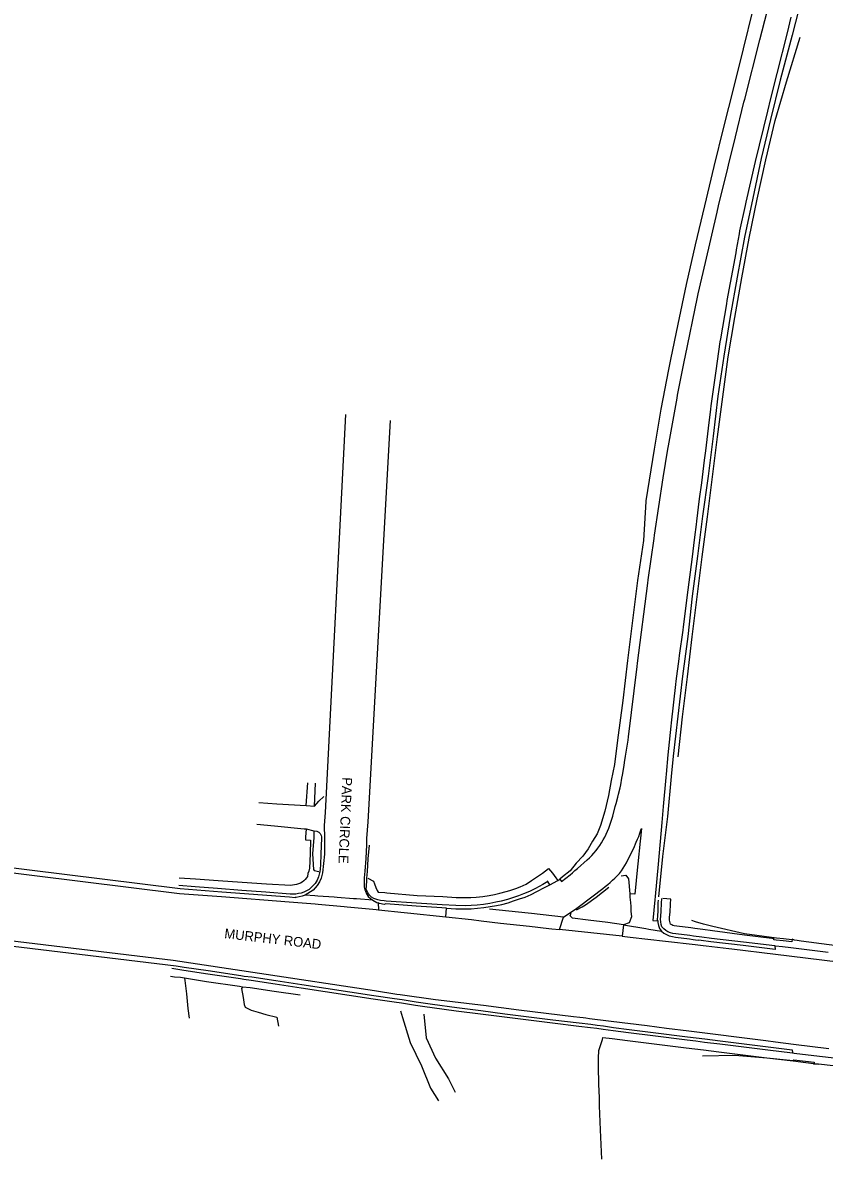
# Model space of a CAD drawing. Extents: x 1723992 to 1732080, y 650782 to 665122.
# Drawn here: x 1725049 to 1725545, y 658514 to 659218 of the extents above; entities that cross this region are included whole.
import ezdxf

# ---------------------------------------------------------------- set-up
doc = ezdxf.new("R2010")
doc.units = 0
for name, color, linetype in [('SURVEY - ROADSIDE BARRIERS with Text', 7, 'Continuous'), ('SURVEY - TRANSPORTATION - Features', 7, 'Continuous'), ('SURVEY - TRANSPORTATION - Roads', 7, 'Continuous'), ('SURVEY - TRANSPORTATION - Roads Text', 7, 'Continuous')]:
    doc.layers.add(name, color=color, linetype=linetype)

msp = doc.modelspace()

# ---------------------------------------------------------------- linework, layer by layer
at = {"layer": 'SURVEY - ROADSIDE BARRIERS with Text'}
for points in [[(1725454.31, 658763.66), (1725456.99, 658788.4), (1725459.98, 658813.11), (1725462.96, 658837.82), (1725466.03, 658862.66), (1725469.2, 658887.44), (1725472.36, 658912.25), (1725475.49, 658937), (1725478.58, 658961.8), (1725481.79, 658986.47), (1725485.28, 659011.19), (1725489.24, 659035.69), (1725493.56, 659060.19), (1725498.27, 659084.82), (1725503.18, 659108.92), (1725508.58, 659133.26), (1725514.22, 659157.6), (1725521.22, 659181.56), (1725529.7, 659209.3)], [(1725527.82, 658649.84), (1725524.68, 658650.2), (1725519.38, 658650.81), (1725515.12, 658651.27), (1725495.31, 658654.08), (1725475.79, 658658.48), (1725469.89, 658660.07), (1725465.02, 658661.42), (1725462.65, 658662.19)], [(1725749.44, 658623.21), (1725747.68, 658622.94), (1725746.17, 658622.95), (1725726.3, 658625.19), (1725706.43, 658627.62), (1725686.58, 658630.08), (1725666.74, 658632.53), (1725646.89, 658635.01), (1725627.04, 658637.46), (1725607.19, 658639.9), (1725587.34, 658642.33), (1725567.5, 658644.8), (1725547.65, 658647.26), (1725530.29, 658649.41), (1725527.82, 658649.88), (1725526.28, 658650.16), (1725524.75, 658650.8)], [(1725469.38, 658578.48), (1725489.23, 658578.95), (1725509.01, 658577.31), (1725525.44, 658575.33), (1725541.17, 658573.4)], [(1725762.72, 658545.48), (1725760.68, 658546.18), (1725739.67, 658549.03), (1725719.83, 658551.53), (1725699.98, 658553.97), (1725680.13, 658556.43), (1725660.28, 658558.86), (1725640.43, 658561.3), (1725620.59, 658563.76), (1725600.74, 658566.22), (1725580.89, 658568.65), (1725561.04, 658571.09), (1725541.17, 658573.41), (1725539.63, 658573.41), (1725538.14, 658573.13)]]:
    msp.add_lwpolyline(points, dxfattribs=at)
at = {"layer": 'SURVEY - TRANSPORTATION - Features'}
for p, q in [((1725224.17, 658733.51), (1725225.12, 658747.48)), ((1725229.25, 658733.05), (1725229.89, 658747.28))]:
    msp.add_line(p, q, dxfattribs=at)
for points in [[(1725530.96, 659234.75), (1725524.82, 659210.53), (1725517.39, 659182.52), (1725511.28, 659158.31), (1725505.65, 659133.97), (1725500.35, 659109.58), (1725495.28, 659085.33), (1725490.85, 659060.69), (1725486.48, 659036.15), (1725482.44, 659011.59), (1725478.8, 658986.89), (1725475.82, 658962.14), (1725472.77, 658937.34), (1725469.21, 658912.63), (1725466.19, 658887.82), (1725463.01, 658863.05), (1725460.29, 658838.18), (1725456.88, 658813.49), (1725454.08, 658788.72), (1725451.23, 658763.96), (1725449.9, 658751.51), (1725447.7, 658726.64), (1725444.57, 658701.81), (1725442.19, 658676.94)], [(1725500.51, 659226.33), (1725494.49, 659202.05), (1725488.39, 659177.82), (1725482.33, 659153.52), (1725476.4, 659129.19), (1725470.51, 659104.86), (1725464.75, 659080.55), (1725459.26, 659056.11), (1725454.01, 659031.55), (1725449.43, 659009.61), (1725448.21, 659003.5), (1725443.6, 658978.83), (1725439.32, 658954.08), (1725434.3, 658922.21), (1725434.2, 658921.72)], [(1725434.2, 658921.72), (1725432.9, 658897.64), (1725429.18, 658872.88), (1725426.08, 658848.07), (1725422.87, 658823.3), (1725419.94, 658798.44), (1725416.68, 658773.89), (1725414.77, 658758.79), (1725412.81, 658748.88), (1725411.09, 658739.69), (1725408.93, 658729.88), (1725406.23, 658721.07), (1725404.11, 658715.95), (1725401.34, 658711.36), (1725398.64, 658706.68), (1725395.19, 658702.16), (1725391.1, 658697.73), (1725387.35, 658693), (1725382.76, 658689.26), (1725380.99, 658687.83)], [(1724297.25, 658787.39), (1725146.15, 658682.02), (1725172, 658680.07), (1725213.89, 658676.86), (1725217.31, 658676.58)], [(1725194.75, 658735.42), (1725205.87, 658734.42), (1725224.17, 658733.51), (1725229.25, 658733.05), (1725231.89, 658736.17), (1725235.07, 658739.04)], [(1725224.09, 658718.95), (1725223.67, 658713.89), (1725223.64, 658712.3), (1725226.89, 658712.07), (1725226.6, 658703.64), (1725226.11, 658694.76), (1725225.7, 658692.77), (1725225.19, 658691.41), (1725225.04, 658689.47), (1725224.24, 658688.6), (1725223.41, 658687.75), (1725222.57, 658686.85), (1725221.6, 658686.08), (1725220.57, 658685.34), (1725219.39, 658684.94), (1725218.18, 658684.6), (1725216.95, 658684.33), (1725215.7, 658684.17), (1725214.58, 658684.03), (1725199.59, 658684.73), (1725184.62, 658685.76), (1725169.64, 658686.9), (1725155.71, 658687.89), (1725145.6, 658688.56)], [(1725193.49, 658721.99), (1725204.59, 658720.78), (1725222.81, 658719.04), (1725224.09, 658718.95), (1725228.9, 658717.87), (1725230.75, 658717.5), (1725231.86, 658716.93), (1725232.8, 658716.03), (1725233.41, 658714.97), (1725233.64, 658714.03), (1725233.66, 658713.45)], [(1724492.49, 658712.89), (1725143.68, 658634.29), (1725147.43, 658633.67), (1725148.68, 658633.43), (1725163.52, 658631.23), (1725183.79, 658628.22), (1725185.77, 658627.89), (1725190.47, 658627.28), (1725205.3, 658625.03), (1725221.41, 658622.63), (1725236.23, 658620.32), (1725251.06, 658618.09), (1725265.89, 658615.82), (1725278.79, 658613.91), (1725283.42, 658613.33), (1725292.15, 658611.97), (1725297.86, 658611.14), (1725302.27, 658610.39), (1725317.27, 658608.35), (1725332.15, 658606.48), (1725347.03, 658604.53), (1725361.91, 658602.7), (1725376.8, 658600.85), (1725393.02, 658598.89), (1725400.17, 658597.98), (1725404.14, 658597.47), (1725408.11, 658596.96), (1725414.26, 658596.09), (1725423.85, 658594.84), (1725438.73, 658592.93), (1725460.13, 658590.3), (1725465.41, 658589.62), (1725470.71, 658588.94), (1725480.29, 658587.75), (1725490.2, 658586.59), (1725509.95, 658584.05), (1725524.76, 658582.19), (1725524.93, 658580.3)], [(1725233.66, 658713.45), (1725233.22, 658703.41), (1725232.94, 658696.68), (1725232.73, 658694.15), (1725232.5, 658692.47), (1725232.33, 658691.69), (1725231.73, 658689.38), (1725230.83, 658687.3), (1725229.63, 658685.16), (1725228.5, 658683.84), (1725227.23, 658682.64), (1725225.89, 658681.49), (1725224.38, 658680.56), (1725222.75, 658679.88), (1725221.08, 658679.28), (1725219.36, 658678.88), (1725217.62, 658678.6), (1725215.86, 658678.53), (1725214.15, 658678.61), (1725199.2, 658679.79), (1725184.24, 658680.91), (1725169.27, 658682.04), (1725155.35, 658683.09), (1725145.24, 658683.84)], [(1725228.9, 658717.87), (1725228.89, 658717.45), (1725228.76, 658713.66), (1725228.05, 658703.59), (1725228.72, 658693.82), (1725229.16, 658693.12), (1725232.05, 658692.63)], [(1725373.61, 658686.36), (1725370.57, 658684.53), (1725365.91, 658682.08), (1725362.33, 658680.31), (1725358.63, 658678.76), (1725355.47, 658677.56), (1725351.69, 658676.26), (1725348.68, 658675.32), (1725344.8, 658674.27), (1725341.45, 658673.52), (1725337.81, 658672.83), (1725333.85, 658672.24), (1725329.86, 658671.85), (1725326.14, 658671.54), (1725322.55, 658671.41), (1725316.73, 658671.46), (1725308.2, 658671.9), (1725292.37, 658673), (1725273.61, 658674.31), (1725272.45, 658674.41), (1725270.08, 658674.69), (1725268.49, 658675.05), (1725266.07, 658675.91), (1725264.62, 658676.79), (1725263.38, 658677.96), (1725262.35, 658679.32), (1725261.64, 658680.86), (1725261.32, 658681.73), (1725261.43, 658683.49), (1725261.57, 658687.05), (1725261.68, 658688.54), (1725262.03, 658692.57), (1725262.57, 658700.51), (1725263.24, 658708.99)], [(1725262.25, 658688.48), (1725265.76, 658686.68), (1725266.49, 658684.94), (1725267.28, 658682.7), (1725268.1, 658680.8), (1725268.68, 658679.82), (1725272.84, 658679.57), (1725274.07, 658679.44), (1725292.8, 658677.79), (1725308.65, 658677.05), (1725317, 658676.58), (1725322.81, 658676.51), (1725325.92, 658676.5), (1725329.35, 658676.77), (1725333.35, 658677.06), (1725337.3, 658677.73), (1725340.64, 658678.27), (1725343.98, 658679.14), (1725347.87, 658680.13), (1725350.09, 658680.93), (1725353.91, 658682.14), (1725356.53, 658683.16), (1725360.15, 658684.86), (1725363.55, 658687.04), (1725367.76, 658689.98), (1725370.37, 658691.55), (1725374.08, 658694.4), (1725376.43, 658691.51), (1725378.56, 658688.78), (1725379.22, 658687.9), (1725379.79, 658687.08)], [(1725418.89, 658689.83), (1725421.79, 658690.39), (1725423.55, 658688.01), (1725424.26, 658678.71)], [(1725374.86, 658684.36), (1725373.61, 658686.36), (1725373.29, 658686.87)], [(1725265.32, 658674.77), (1725255.35, 658675.61), (1725253.36, 658675.78), (1725243.39, 658676.55), (1725241.4, 658676.7), (1725231.42, 658677.34), (1725229.42, 658677.49), (1725223.48, 658678.04)], [(1725391.41, 658668.83), (1725394.93, 658670.77), (1725396.99, 658671.86), (1725403.62, 658676.69), (1725411.42, 658682.86)], [(1725547.04, 658642.38), (1725527.2, 658644.87), (1725524.06, 658645.26), (1725518.77, 658645.92), (1725514.52, 658646.46), (1725514.02, 658646.52), (1725494.66, 658648.8), (1725474.82, 658651.17), (1725468.8, 658651.87), (1725463.84, 658652.54), (1725461.44, 658652.91), (1725452.86, 658653.92), (1725451.02, 658654.26), (1725449.45, 658654.64), (1725447.94, 658655.22), (1725446.54, 658656.04), (1725445.3, 658657.1), (1725444.23, 658658.34), (1725443.66, 658659.88), (1725443.43, 658661.47), (1725443.37, 658663.01), (1725443.46, 658665), (1725443.76, 658668.12), (1725443.96, 658673), (1725444.14, 658675.9)], [(1725524.75, 658650.8), (1725524.55, 658649.04), (1725519.24, 658649.66), (1725514.98, 658650.12), (1725513.38, 658650.37), (1725513.35, 658651.05), (1725512.13, 658651.14), (1725495.2, 658653.19), (1725475.45, 658655.89), (1725469.44, 658656.69), (1725464.48, 658657.36), (1725462.07, 658657.68), (1725453.5, 658658.69), (1725451.88, 658658.99), (1725451.04, 658659.18), (1725450.32, 658659.51), (1725449.59, 658660.06), (1725449.25, 658660.9), (1725449.09, 658661.74), (1725448.99, 658662.48), (1725448.99, 658664.39), (1725449.29, 658667.51), (1725449.49, 658672.39), (1725449.51, 658672.62), (1725449.69, 658675.55), (1725444.71, 658675.86)], [(1725310.93, 658669.87), (1725308.04, 658670.07), (1725292.2, 658671.04), (1725273.45, 658672.49), (1725272.28, 658672.2), (1725269.58, 658672.84), (1725268.74, 658673.11)], [(1725383.35, 658664.29), (1725363.48, 658666.56), (1725361.5, 658666.78), (1725337.53, 658669.3)], [(1725441.59, 658661.99), (1725441.54, 658662.75), (1725441.62, 658665.2), (1725441.92, 658668.33), (1725441.94, 658673.22), (1725441.99, 658674.95)], [(1725420.35, 658659.65), (1725410.81, 658660.98), (1725398.64, 658662.48), (1725388.8, 658663.78), (1725387.43, 658665.05), (1725388.14, 658666.76)], [(1725441.59, 658661.99), (1725441.66, 658660.93), (1725442, 658659.07)], [(1725420.35, 658659.65), (1725434.16, 658657.34), (1725436.12, 658656.98), (1725443.89, 658655.75)], [(1725442, 658659.07), (1725442.63, 658657.22), (1725443.89, 658655.75), (1725445.36, 658654.48), (1725447.02, 658653.5), (1725448.78, 658652.72), (1725450.65, 658652.26), (1725452.59, 658651.9), (1725461.17, 658650.89), (1725463.57, 658650.52), (1725465.05, 658650.36), (1725467.05, 658650.08)], [(1725514.02, 658646.52), (1725514.27, 658644.4), (1725494.4, 658646.72), (1725474.54, 658649.1), (1725468.53, 658649.85), (1725467.05, 658650.08)], [(1725220.45, 658616.11), (1725204.3, 658618.25), (1725189.47, 658620.49), (1725184.75, 658620.97), (1725182.77, 658621.3), (1725162.5, 658624.31), (1725148.84, 658626.46), (1725146.43, 658626.9), (1725142.63, 658627.15), (1725140.21, 658627.52)], [(1725140.98, 658632.75), (1725143.4, 658632.36), (1725147.14, 658631.74), (1725148.4, 658631.5), (1725163.24, 658629.3), (1725183.51, 658626.29), (1725185.48, 658625.96), (1725190.17, 658625.26), (1725205, 658623.02), (1725221.12, 658620.67), (1725235.94, 658618.36), (1725250.77, 658616.12), (1725265.59, 658613.84), (1725278.49, 658611.93), (1725283.11, 658611.28), (1725291.85, 658609.91), (1725297.55, 658609.08), (1725301.97, 658608.38), (1725317.01, 658606.33), (1725331.9, 658604.47), (1725346.77, 658602.52), (1725361.66, 658600.71), (1725376.54, 658598.86), (1725392.77, 658596.89), (1725399.93, 658596.05), (1725403.9, 658595.55), (1725407.86, 658595.03), (1725414.01, 658594.16), (1725423.61, 658592.92), (1725438.49, 658591.01), (1725459.89, 658588.37), (1725465.16, 658587.69), (1725470.47, 658587.01), (1725480.05, 658585.83), (1725489.95, 658584.6), (1725509.68, 658582.1), (1725524.93, 658580.3), (1725526.11, 658580.16), (1725541.79, 658578.29), (1725561.65, 658575.91)], [(1725148.84, 658626.46), (1725148.97, 658625.04), (1725150.1, 658616.78), (1725150.89, 658607.76), (1725151.69, 658601.85)], [(1725184.75, 658620.97), (1725184.18, 658620.25), (1725185.16, 658614.59), (1725185.84, 658610.19), (1725186.28, 658608.55), (1725190.17, 658606.65), (1725194.42, 658605.58), (1725199.23, 658604.05), (1725206.06, 658602.47), (1725207.04, 658596.77)], [(1725282.39, 658606.39), (1725283.79, 658602.12), (1725288.52, 658586.79), (1725295.49, 658572.31), (1725301, 658558.37), (1725305.9, 658550.63)], [(1725296.83, 658604.19), (1725298.32, 658589.58), (1725304.22, 658576.97), (1725312.15, 658564.17), (1725316.34, 658556.06)], [(1725407.05, 658514.42), (1725406.11, 658532.59), (1725405.69, 658547.58), (1725405.6, 658552.77), (1725405.16, 658560.76), (1725404.94, 658572.02), (1725404.9, 658577.02), (1725405.12, 658581.79), (1725407.36, 658588.68), (1725407.72, 658589.91), (1725413.38, 658589.19), (1725422.98, 658587.95), (1725437.86, 658586.06), (1725459.26, 658583.44), (1725464.53, 658582.74), (1725469.84, 658582.1), (1725479.42, 658580.9), (1725489.32, 658579.68), (1725509.01, 658577.31), (1725525.47, 658575.59), (1725525.74, 658575.98), (1725538.36, 658574.49), (1725538.14, 658573.13)]]:
    msp.add_lwpolyline(points, dxfattribs=at)
at = {"layer": 'SURVEY - TRANSPORTATION - Roads'}
msp.add_line((1725419.59, 658652.58), (1725380.84, 658656.61), dxfattribs=at)
for points in [[(1725276, 658971.88), (1725262.29, 658723.45), (1725261.42, 658713.01), (1725261.36, 658709.1), (1725261.11, 658700.6), (1725260.42, 658692.71), (1725260.05, 658688.68), (1725260.04, 658687.19), (1725259.98, 658683.08), (1725260.43, 658681.35), (1725260.76, 658680.41), (1725261.49, 658678.72), (1725262.47, 658677.15), (1725263.82, 658675.86), (1725265.32, 658674.77), (1725267.81, 658673.41), (1725268.74, 658673.11), (1725268.8, 658668.86), (1725284.72, 658667.29), (1725286.71, 658667.09), (1725310.58, 658664.59), (1725310.93, 658669.87), (1725316.63, 658669.49), (1725322.44, 658669.45), (1725326.22, 658669.58), (1725330.07, 658669.9), (1725334.05, 658670.29), (1725338.01, 658670.88), (1725341.78, 658671.58), (1725345.15, 658672.24), (1725349.03, 658673.27), (1725352.33, 658674.38), (1725356.11, 658675.68), (1725359.59, 658676.76), (1725363.22, 658678.43), (1725366.82, 658680.18), (1725371.54, 658682.64), (1725374.86, 658684.36), (1725379.79, 658687.08), (1725380.99, 658687.83), (1725382.03, 658686.48), (1725387.35, 658690.57), (1725388.89, 658691.86), (1725390.42, 658693.14), (1725391.93, 658694.46), (1725397.91, 658699.77), (1725399.38, 658701.12), (1725400.77, 658702.56), (1725402.13, 658704.02), (1725403.44, 658705.54), (1725404.65, 658707.13), (1725405.79, 658708.76), (1725406.88, 658710.44), (1725407.91, 658712.15), (1725408.85, 658713.92), (1725409.75, 658715.71), (1725410.59, 658717.52), (1725411.38, 658719.36), (1725412.08, 658721.23), (1725412.7, 658723.13), (1725413.28, 658725.04), (1725413.83, 658726.96), (1725415.37, 658732.76), (1725415.88, 658734.7), (1725416.93, 658738.56), (1725417.41, 658740.5), (1725418.33, 658744.39), (1725418.77, 658746.34), (1725419.4, 658750.29), (1725419.73, 658752.26), (1725420.77, 658758.17), (1725421.1, 658760.14), (1725421.71, 658764.09), (1725423.26, 658773.97), (1725423.52, 658775.95), (1725428.84, 658819.6), (1725429.08, 658821.58), (1725435.5, 658871.13), (1725435.76, 658873.11), (1725439.37, 658898.84), (1725439.66, 658900.82), (1725445.02, 658936.39), (1725447.93, 658954.14), (1725448.26, 658956.11), (1725453.56, 658985.62), (1725453.93, 658987.58), (1725458.12, 659009.16), (1725458.52, 659011.12), (1725466.29, 659048.29), (1725466.72, 659050.24), (1725471.11, 659069.74), (1725478.39, 659100.87), (1725479.31, 659104.76), (1725484.9, 659128.09), (1725485.37, 659130.03), (1725489.67, 659147.5), (1725494.92, 659168.85), (1725495.41, 659170.79), (1725504.75, 659207.61), (1725509.23, 659225.03)], [(1725524.06, 659221.53), (1725521.59, 659211.84), (1725515.24, 659186.64), (1725511.37, 659171.12), (1725509.43, 659163.36), (1725501.91, 659132.27), (1725496.04, 659106.96), (1725495.62, 659105.01), (1725492.29, 659089.37), (1725491.93, 659087.4), (1725490.24, 659077.55), (1725489.89, 659075.58), (1725484.44, 659046.1), (1725484.11, 659044.13), (1725480.44, 659022.45), (1725480.11, 659020.48), (1725477.56, 659002.68), (1725474.53, 658980.9), (1725474.26, 658978.92), (1725472.8, 658967.02), (1725471.09, 658953.14), (1725470.35, 658947.19), (1725468.6, 658933.31), (1725467.35, 658923.4), (1725465.68, 658909.51), (1725465.43, 658907.53), (1725464.41, 658899.6), (1725462.65, 658885.73), (1725459.82, 658863.93), (1725459.56, 658861.95), (1725457.31, 658844.11), (1725457.05, 658842.13), (1725454.88, 658826.3), (1725454.61, 658824.32), (1725452.89, 658810.44), (1725452.65, 658808.46), (1725449.99, 658784.63), (1725449.78, 658782.64), (1725448.32, 658768.73), (1725447.94, 658764.75), (1725446.79, 658752.81), (1725446.6, 658750.82), (1725444.96, 658732.89), (1725444.12, 658722.93), (1725441.82, 658697.04), (1725439.97, 658677.14), (1725439.84, 658675.16), (1725438.59, 658662.24), (1725441.59, 658661.99)], [(1725248.53, 658975.65), (1725235.77, 658729.05), (1725235.2, 658721.06), (1725235.44, 658713.37), (1725235.41, 658703.33), (1725234.2, 658691.86), (1725233.99, 658691.02), (1725233.4, 658688.44), (1725232.38, 658686.18), (1725231.01, 658683.87), (1725229.74, 658682.46), (1725228.35, 658681.14), (1725226.83, 658679.96), (1725225.22, 658678.89), (1725223.48, 658678.04), (1725221.65, 658677.38), (1725219.77, 658676.9), (1725217.85, 658676.6), (1725217.31, 658676.58)], [(1724300.1, 658784.01), (1725145.85, 658679.03), (1725171.78, 658677.08), (1725213.66, 658673.87), (1725229.6, 658672.56), (1725231.6, 658672.39), (1725247.53, 658670.98), (1725249.52, 658670.79), (1725265.45, 658669.23), (1725267.44, 658669.02), (1725268.8, 658668.86)], [(1725380.84, 658656.61), (1725383.35, 658664.29), (1725391.57, 658670), (1725393.2, 658671.15), (1725407.56, 658682), (1725409.13, 658683.25), (1725410.67, 658684.52), (1725412.18, 658685.83), (1725413.68, 658687.16), (1725415.16, 658688.5), (1725416.61, 658689.88), (1725417.93, 658691.37), (1725419.15, 658692.96), (1725420.27, 658694.61), (1725421.32, 658696.31), (1725422.32, 658698.04), (1725423.19, 658699.84), (1725424.07, 658701.64), (1725425.89, 658705.2), (1725426.76, 658707), (1725428.35, 658710.67), (1725429.11, 658712.52), (1725429.86, 658714.37), (1725430.58, 658716.24), (1725431.19, 658718.14), (1725431.64, 658719.31), (1725431.05, 658713.34), (1725430.84, 658711.35), (1725429.31, 658697.44), (1725429.11, 658695.45), (1725427.44, 658678.48), (1725424.26, 658678.71), (1725424.26, 658678.71), (1725424.39, 658676.7), (1725424.67, 658673.42), (1725424.9, 658670.85), (1725425.06, 658668.07), (1725425.38, 658664.44), (1725424.02, 658660.83), (1725420.35, 658659.65), (1725419.59, 658652.58)], [(1724492.85, 658715.87), (1725141.86, 658637.67)], [(1725310.58, 658664.59), (1725326.48, 658662.78), (1725332.44, 658662.09), (1725344.36, 658660.71), (1725362.25, 658658.67), (1725374.17, 658657.3), (1725376.15, 658657.08), (1725380.84, 658656.61)], [(1725419.59, 658652.58), (1725424.64, 658651.97), (1725446.5, 658649.52), (1725464.68, 658647.49)], [(1725464.68, 658647.49), (1725469.64, 658646.81), (1725471.59, 658646.54), (1725485.5, 658644.92), (1725487.48, 658644.69), (1725514.54, 658641.45), (1725603.86, 658630.44), (1725726.92, 658615.27), (1725763.1, 658610.81), (1725790.88, 658607.34), (1725824.61, 658603.14), (1725872.23, 658597.26), (1725919.71, 658591.4)], [(1725141.86, 658637.67), (1725195.26, 658629.58), (1725266.45, 658618.83), (1725280.3, 658616.73), (1725282.28, 658616.45), (1725304.07, 658613.4), (1725306.05, 658613.15), (1725331.87, 658610.06), (1725333.85, 658609.82), (1725355.67, 658607.02), (1725389.42, 658602.86), (1725393.39, 658602.39), (1725395.38, 658602.15), (1725397.11, 658601.91), (1725399.35, 658601.66), (1725421.18, 658598.99), (1725423.17, 658598.74), (1725435.06, 658597.19), (1725446.97, 658595.69), (1725460.85, 658593.92), (1725508.47, 658587.88), (1725514.43, 658587.13), (1725525.68, 658585.72), (1725547.51, 658582.99)]]:
    msp.add_lwpolyline(points, dxfattribs=at)

# ---------------------------------------------------------------- texts
at = {"layer": 'SURVEY - TRANSPORTATION - Roads Text'}
for s, rotation, p in [('PARK CIRCLE', 267.35024, (1725246.58, 658751.06)), ('MURPHY ROAD ', 353.37384, (1725173.27, 658651.38))]:
    msp.add_text(s, height=6, rotation=rotation, dxfattribs=at).set_placement(p)

doc.saveas('drawing.dxf')
